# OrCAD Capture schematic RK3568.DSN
size A3; title: 野火_EBF RK3568 底板; rev: V1.0; note: MXM连接器; note: https://yehuosm.tmall.com
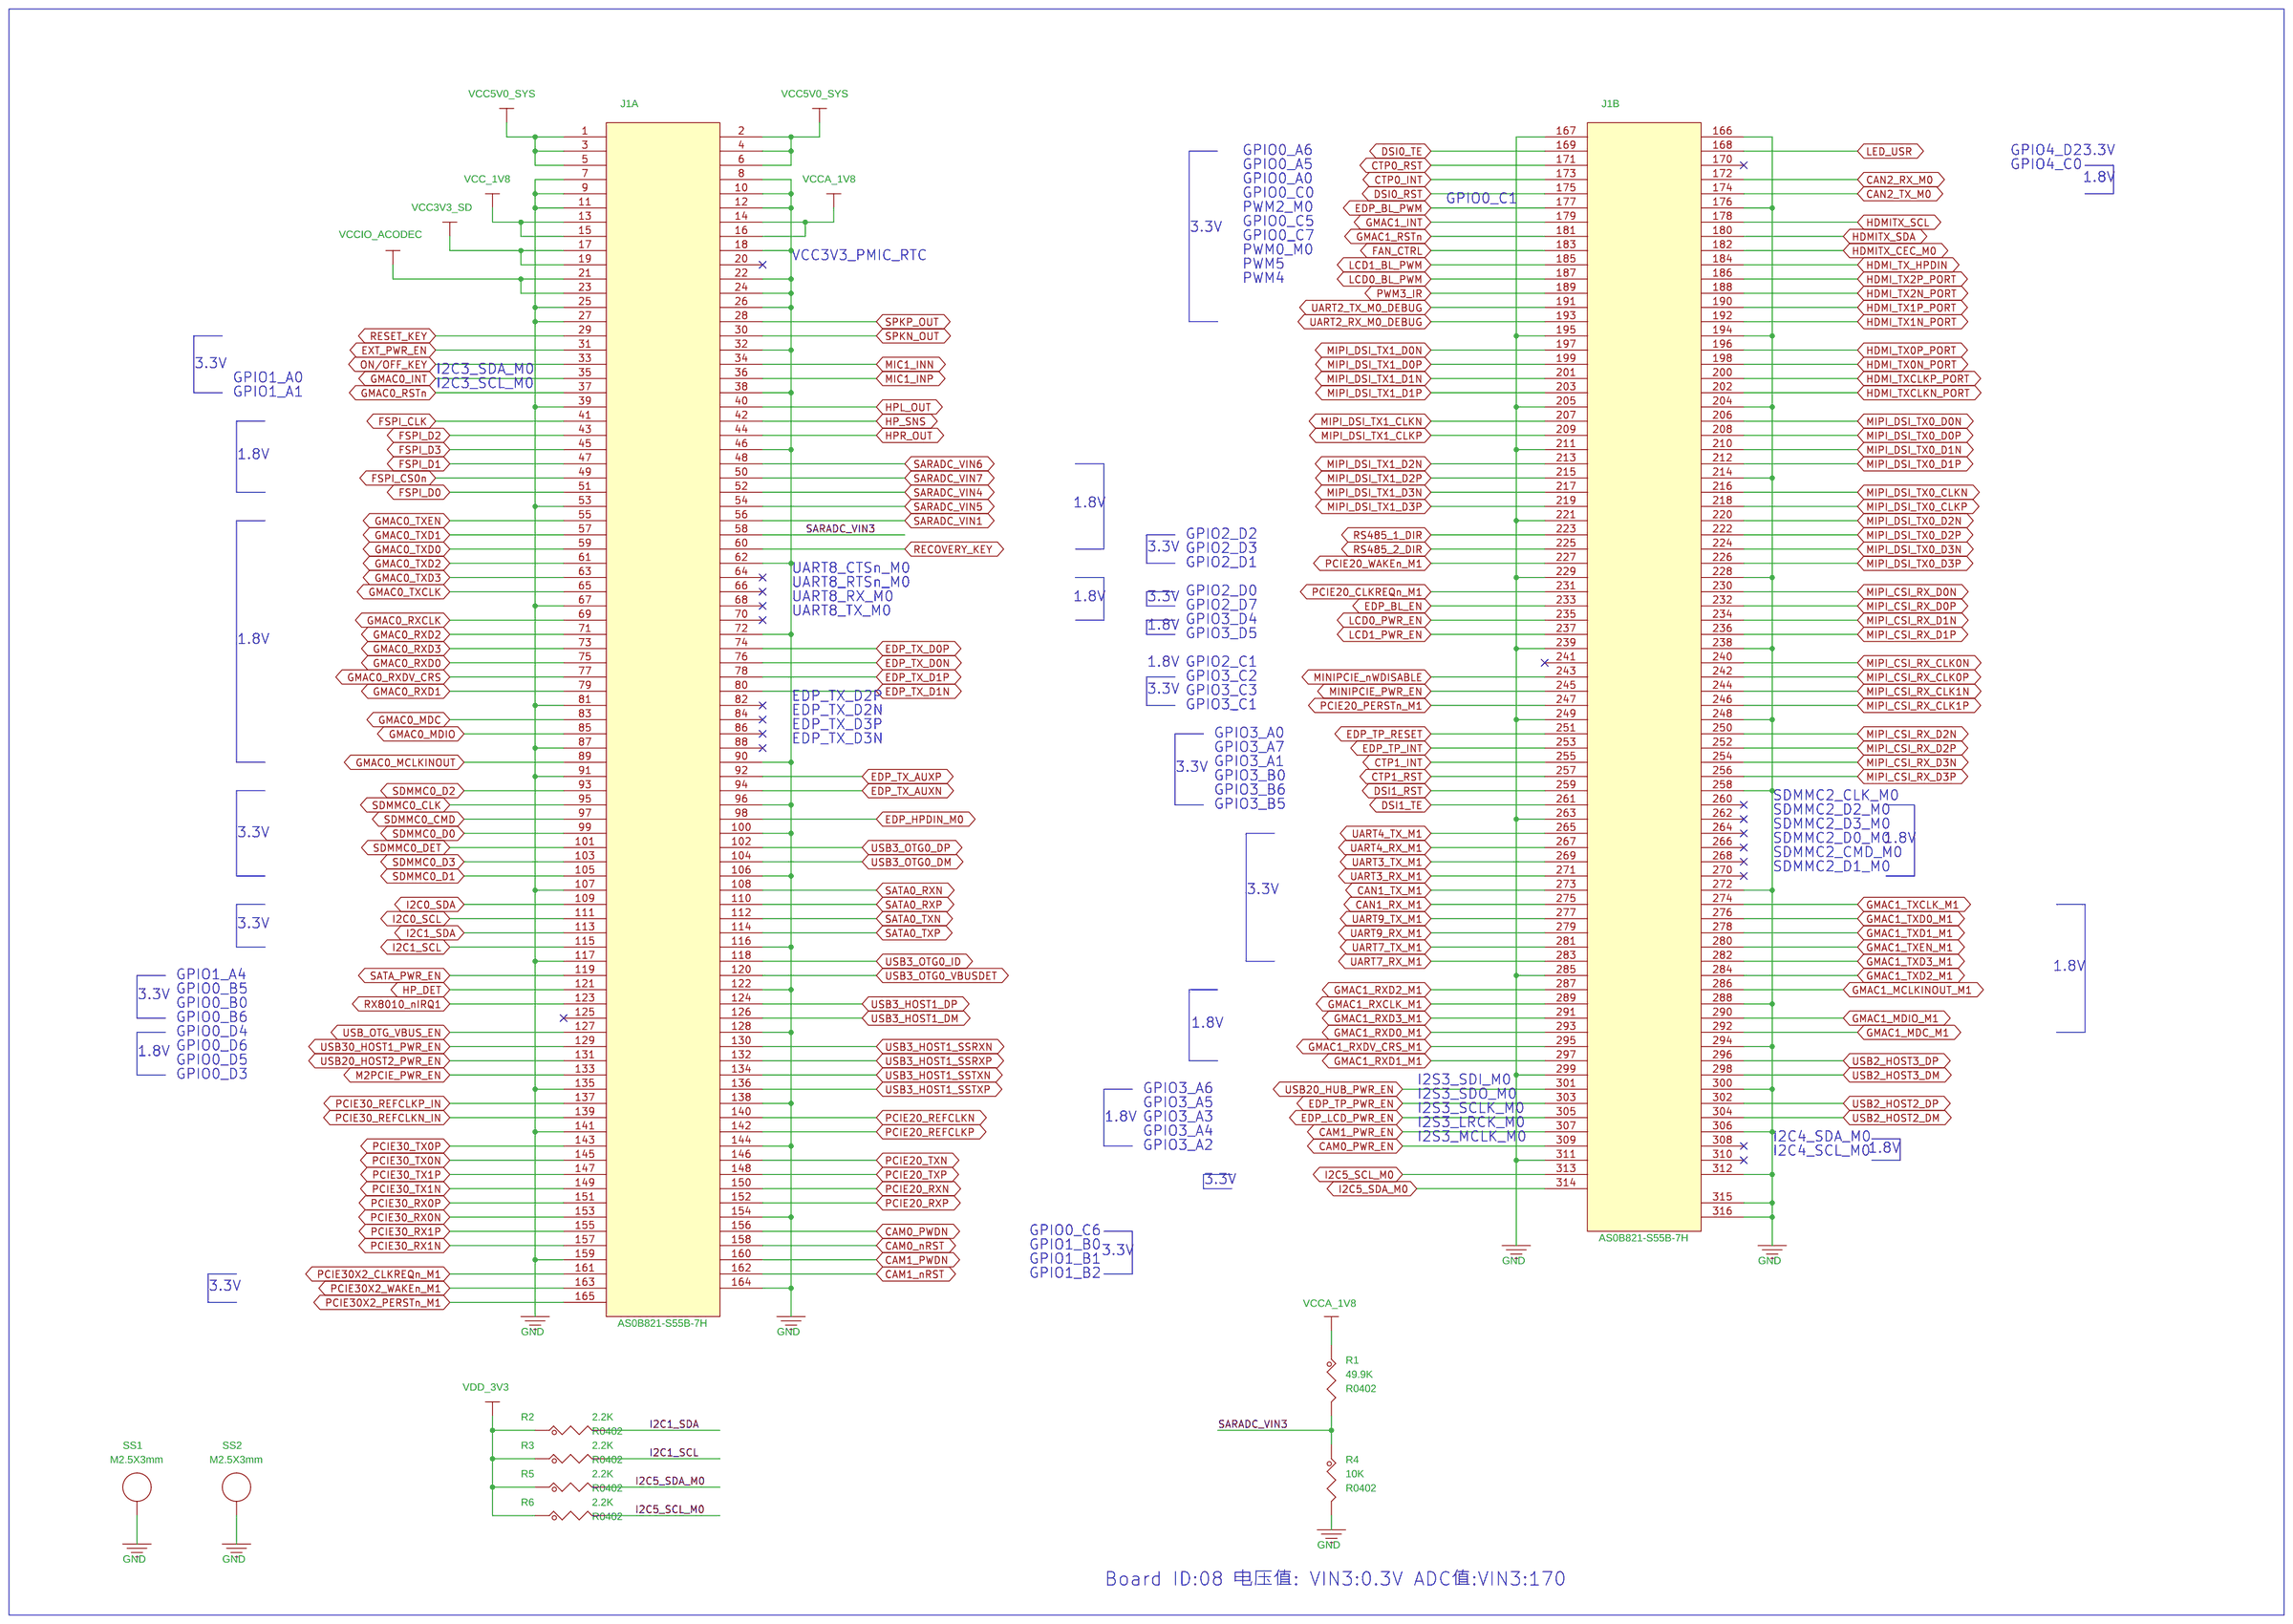
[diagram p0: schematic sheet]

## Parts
J1  AS0B821-S55B-7H  [AS0B821-S55B-7H]  (sections A,B)
R1  49.9K  [R0402]
R2  2.2K  [R0402]
R3  2.2K  [R0402]
R4  10K  [R0402]
R5  2.2K  [R0402]
R6  2.2K  [R0402]
SS1  M2.5X3mm  [SMTSO-M2r5]
SS2  M2.5X3mm  [SMTSO-M2r5]

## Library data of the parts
J1 = AS0B821-S55B-7H: 规格书: AS0B821-S55B-7H.pdf; 类别: 金手指连接器; 生命周期: 量产; 条码: EBF29040084
R1 = RES: 规格: 贴片电阻49.9K 1% 1/16W 0402; 规格编号: RMC040249.9K1%N; 规格书: 幸亚电阻.pdf; 价格: 0.015936; 类别: 贴片电阻0402; 品牌: 幸亚; 生命周期: 量产; 条码: EBF29070257
R2 R3 R5 R6 = RES: 规格: 贴片电阻2.2K 1% 1/16W 0402; 规格编号: RI0402L2201FT; 规格书: 合科泰-RI系列电阻.pdf; 类别: 贴片电阻0402; 品牌: 合科泰; 生命周期: 量产; 条码: EBF29070051
R4 = RES: 规格: 贴片电阻10K 1% 1/16W 0402; 规格编号: 0402WGF1002TCE; 规格书: 厚声-无铅厚膜电阻.pdf; 价格: 0.002773; 类别: 贴片电阻0402; 品牌: 厚声; 生命周期: 量产; 条码: EBF29070046
SS1 SS2 = SPACER: 规格: SMT贴片螺母M2.5 台阶高度1.4MM 台阶外径：4.09MM 螺柱长度：3MM; 规格编号: SMTSO2530CTJ; 规格书: 雄和远景_SMTSO2530CTJ.pdf; 类别: 贴片螺母; 品牌: 雄和远景; 生命周期: 量产; 条码: EBFCIS221028102827

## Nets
GND: J1.7 J1.8 J1.9 J1.10 J1.11 J1.12 J1.18 J1.22 J1.24 J1.25 J1.26 J1.27 J1.32 J1.38 J1.39 J1.46 J1.53 J1.62 J1.67 J1.72 J1.81 J1.87 J1.90 J1.91 J1.96 J1.100 J1.106 J1.107 J1.116 J1.117 J1.122 J1.128 J1.135 J1.138 J1.141 J1.144 J1.154 J1.159 J1.164 J1.166 J1.167 J1.176 J1.194 J1.195 J1.204 J1.205 J1.211 J1.214 J1.221 J1.228 J1.229 J1.238 J1.239 J1.248 J1.249 J1.258 J1.263 J1.272 J1.285 J1.288 J1.294 J1.299 J1.300 J1.306 J1.311 J1.312 J1.315 J1.316 R4.2 SS1.1(NC) SS2.1(NC)
VCC3V3_SD: J1.17 J1.19
VCC5V0_SYS: J1.1 J1.2 J1.3 J1.4 J1.5 J1.6
VCC_1V8: J1.13 J1.15
VCCA_1V8: J1.14 J1.16 R1.1
VCCIO_ACODEC: J1.21 J1.23
VDD_3V3: R2.1 R3.1 R5.1 R6.1
CAM0_nRST: J1.158
CAM0_PWDN: J1.156
CAM0_PWR_EN: J1.309
CAM1_nRST: J1.162
CAM1_PWDN: J1.160
CAM1_PWR_EN: J1.307
CAN1_RX_M1: J1.275
CAN1_TX_M1: J1.273
CAN2_RX_M0: J1.172
CAN2_TX_M0: J1.174
CTP0_INT: J1.173
CTP0_RST: J1.171
CTP1_INT: J1.255
CTP1_RST: J1.257
DSI0_RST: J1.175
DSI0_TE: J1.169
DSI1_RST: J1.259
DSI1_TE: J1.261
EDP_BL_EN: J1.233
EDP_BL_PWM: J1.177
EDP_HPDIN_M0: J1.98
EDP_LCD_PWR_EN: J1.305
EDP_TP_INT: J1.253
EDP_TP_PWR_EN: J1.303
EDP_TP_RESET: J1.251
EDP_TX_AUXN: J1.94
EDP_TX_AUXP: J1.92
EDP_TX_D0N: J1.76
EDP_TX_D0P: J1.74
EDP_TX_D1N: J1.80
EDP_TX_D1P: J1.78
EXT_PWR_EN: J1.31
FAN_CTRL: J1.183
FSPI_CLK: J1.41
FSPI_CS0n: J1.49
FSPI_D0: J1.51
FSPI_D1: J1.47
FSPI_D2: J1.43
FSPI_D3: J1.45
GMAC0_INT: J1.35
GMAC0_MCLKINOUT: J1.89
GMAC0_MDC: J1.83
GMAC0_MDIO: J1.85
GMAC0_RSTn: J1.37
GMAC0_RXCLK: J1.69
GMAC0_RXD0: J1.75
GMAC0_RXD1: J1.79
GMAC0_RXD2: J1.71
GMAC0_RXD3: J1.73
GMAC0_RXDV_CRS: J1.77
GMAC0_TXCLK: J1.65
GMAC0_TXD0: J1.59
GMAC0_TXD1: J1.57
GMAC0_TXD2: J1.61
GMAC0_TXD3: J1.63
GMAC0_TXEN: J1.55
GMAC1_INT: J1.179
GMAC1_MCLKINOUT_M1: J1.286
GMAC1_MDC_M1: J1.292
GMAC1_MDIO_M1: J1.290
GMAC1_RSTn: J1.181
GMAC1_RXCLK_M1: J1.289
GMAC1_RXD0_M1: J1.293
GMAC1_RXD1_M1: J1.297
GMAC1_RXD2_M1: J1.287
GMAC1_RXD3_M1: J1.291
GMAC1_RXDV_CRS_M1: J1.295
GMAC1_TXCLK_M1: J1.274
GMAC1_TXD0_M1: J1.276
GMAC1_TXD1_M1: J1.278
GMAC1_TXD2_M1: J1.284
GMAC1_TXD3_M1: J1.282
GMAC1_TXEN_M1: J1.280
HDMI_TX0N_PORT: J1.198
HDMI_TX0P_PORT: J1.196
HDMI_TX1N_PORT: J1.192
HDMI_TX1P_PORT: J1.190
HDMI_TX2N_PORT: J1.188
HDMI_TX2P_PORT: J1.186
HDMI_TX_HPDIN: J1.184
HDMI_TXCLKN_PORT: J1.202
HDMI_TXCLKP_PORT: J1.200
HDMITX_CEC_M0: J1.182
HDMITX_SCL: J1.178
HDMITX_SDA: J1.180
HP_DET: J1.121
HP_SNS: J1.42
HPL_OUT: J1.40
HPR_OUT: J1.44
I2C0_SCL: J1.111
I2C0_SDA: J1.109
I2C1_SCL: J1.115 R3.2
I2C1_SDA: J1.113 R2.2
I2C5_SCL_M0: J1.313 R6.2
I2C5_SDA_M0: J1.314 R5.2
LCD0_BL_PWM: J1.187
LCD0_PWR_EN: J1.235
LCD1_BL_PWM: J1.185
LCD1_PWR_EN: J1.237
LED_USR: J1.168
M2PCIE_PWR_EN: J1.133
MIC1_INN: J1.34
MIC1_INP: J1.36
MINIPCIE_nWDISABLE: J1.243
MINIPCIE_PWR_EN: J1.245
MIPI_CSI_RX_CLK0N: J1.240
MIPI_CSI_RX_CLK0P: J1.242
MIPI_CSI_RX_CLK1N: J1.244
MIPI_CSI_RX_CLK1P: J1.246
MIPI_CSI_RX_D0N: J1.230
MIPI_CSI_RX_D0P: J1.232
MIPI_CSI_RX_D1N: J1.234
MIPI_CSI_RX_D1P: J1.236
MIPI_CSI_RX_D2N: J1.250
MIPI_CSI_RX_D2P: J1.252
MIPI_CSI_RX_D3N: J1.254
MIPI_CSI_RX_D3P: J1.256
MIPI_DSI_TX0_CLKN: J1.216
MIPI_DSI_TX0_CLKP: J1.218
MIPI_DSI_TX0_D0N: J1.206
MIPI_DSI_TX0_D0P: J1.208
MIPI_DSI_TX0_D1N: J1.210
MIPI_DSI_TX0_D1P: J1.212
MIPI_DSI_TX0_D2N: J1.220
MIPI_DSI_TX0_D2P: J1.222
MIPI_DSI_TX0_D3N: J1.224
MIPI_DSI_TX0_D3P: J1.226
MIPI_DSI_TX1_CLKN: J1.207
MIPI_DSI_TX1_CLKP: J1.209
MIPI_DSI_TX1_D0N: J1.197
MIPI_DSI_TX1_D0P: J1.199
MIPI_DSI_TX1_D1N: J1.201
MIPI_DSI_TX1_D1P: J1.203
MIPI_DSI_TX1_D2N: J1.213
MIPI_DSI_TX1_D2P: J1.215
MIPI_DSI_TX1_D3N: J1.217
MIPI_DSI_TX1_D3P: J1.219
ON/OFF_KEY: J1.33
PCIE20_CLKREQn_M1: J1.231
PCIE20_PERSTn_M1: J1.247
PCIE20_REFCLKN: J1.140
PCIE20_REFCLKP: J1.142
PCIE20_RXN: J1.150
PCIE20_RXP: J1.152
PCIE20_TXN: J1.146
PCIE20_TXP: J1.148
PCIE20_WAKEn_M1: J1.227
PCIE30_REFCLKN_IN: J1.139
PCIE30_REFCLKP_IN: J1.137
PCIE30_RX0N: J1.153
PCIE30_RX0P: J1.151
PCIE30_RX1N: J1.157
PCIE30_RX1P: J1.155
PCIE30_TX0N: J1.145
PCIE30_TX0P: J1.143
PCIE30_TX1N: J1.149
PCIE30_TX1P: J1.147
PCIE30X2_CLKREQn_M1: J1.161
PCIE30X2_PERSTn_M1: J1.165
PCIE30X2_WAKEn_M1: J1.163
PWM3_IR: J1.189
RECOVERY_KEY: J1.60
RESET_KEY: J1.29
RS485_1_DIR: J1.223
RS485_2_DIR: J1.225
RX8010_nIRQ1: J1.123
SARADC_VIN1: J1.56
SARADC_VIN3: J1.58 R1.2 R4.1
SARADC_VIN4: J1.52
SARADC_VIN5: J1.54
SARADC_VIN6: J1.48
SARADC_VIN7: J1.50
SATA0_RXN: J1.108
SATA0_RXP: J1.110
SATA0_TXN: J1.112
SATA0_TXP: J1.114
SATA_PWR_EN: J1.119
SDMMC0_CLK: J1.95
SDMMC0_CMD: J1.97
SDMMC0_D0: J1.99
SDMMC0_D1: J1.105
SDMMC0_D2: J1.93
SDMMC0_D3: J1.103
SDMMC0_DET: J1.101
SPKN_OUT: J1.30
SPKP_OUT: J1.28
UART2_RX_M0_DEBUG: J1.193
UART2_TX_M0_DEBUG: J1.191
UART3_RX_M1: J1.271
UART3_TX_M1: J1.269
UART4_RX_M1: J1.267
UART4_TX_M1: J1.265
UART7_RX_M1: J1.283
UART7_TX_M1: J1.281
UART9_RX_M1: J1.279
UART9_TX_M1: J1.277
USB2_HOST2_DM: J1.304
USB2_HOST2_DP: J1.302
USB2_HOST3_DM: J1.298
USB2_HOST3_DP: J1.296
USB3_HOST1_DM: J1.126
USB3_HOST1_DP: J1.124
USB3_HOST1_SSRXN: J1.130
USB3_HOST1_SSRXP: J1.132
USB3_HOST1_SSTXN: J1.134
USB3_HOST1_SSTXP: J1.136
USB3_OTG0_DM: J1.104
USB3_OTG0_DP: J1.102
USB3_OTG0_ID: J1.118
USB3_OTG0_VBUSDET: J1.120
USB20_HOST2_PWR_EN: J1.131
USB20_HUB_PWR_EN: J1.301
USB30_HOST1_PWR_EN: J1.129
USB_OTG_VBUS_EN: J1.127

Not connected (* = marked no-connect by the designer): J1 20* 64* 66* 68* 70* 82* 84* 86* 88* 125* 170* 241* 260* 262* 264* 266* 268* 270* 308* 310*

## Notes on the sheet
- GPIO0_A6
- GPIO4_D2
- 3.3V
- GPIO0_A5
- GPIO4_C0
- GPIO0_A0
- 1.8V
- GPIO0_C0
- GPIO0_C1
- GPIO0_C5
- PWM2_M0
- 3.3V
- GPIO0_C7
- VCC3V3_PMIC_RTC
- PWM0_M0
- PWM5
- PWM4
- 3.3V
- I2C3_SDA_M0
- GPIO1_A0
- I2C3_SCL_M0
- GPIO1_A1
- 1.8V
- 1.8V
- GPIO2_D2
- 3.3V
- GPIO2_D3
- UART8_CTSn_M0
- GPIO2_D1
- UART8_RTSn_M0
- GPIO2_D0
- UART8_RX_M0
- 1.8V
- 3.3V
- GPIO2_D7
- UART8_TX_M0
- 1.8V
- GPIO3_D4
- 1.8V
- GPIO3_D5
- 1.8V
- GPIO2_C1
- 3.3V
- GPIO3_C2
- GPIO3_C3
- EDP_TX_D2P
- GPIO3_C1
- EDP_TX_D2N
- EDP_TX_D3P
- EDP_TX_D3N
- GPIO3_A0
- GPIO3_A7
- 3.3V
- GPIO3_A1
- GPIO3_B0
- GPIO3_B6
- GPIO3_B5
- SDMMC2_CLK_M0
- SDMMC2_D2_M0
- SDMMC2_D3_M0
- 3.3V
- SDMMC2_D0_M0
- 1.8V
- SDMMC2_CMD_M0
- SDMMC2_D1_M0
- 3.3V
- 3.3V
- GPIO1_A4
- 1.8V
- GPIO0_B5
- 3.3V
- GPIO0_B0
- GPIO0_B6
- 1.8V
- GPIO0_D4
- 1.8V
- GPIO0_D5
- GPIO0_D6
- GPIO0_D3
- GPIO3_A6
- I2S3_SDI_M0
- I2S3_SDO_M0
- GPIO3_A5
- I2S3_SCLK_M0
- 1.8V
- GPIO3_A3
- I2S3_LRCK_M0
- GPIO3_A2
- GPIO3_A4
- I2S3_MCLK_M0
- I2C4_SDA_M0
- I2C4_SCL_M0
- 1.8V
- 3.3V
- GPIO0_C6
- GPIO1_B0
- GPIO1_B1
- 3.3V
- GPIO1_B2
- 3.3V
- Board ID:08 电压值: VIN3:0.3V ADC值:VIN3:170
